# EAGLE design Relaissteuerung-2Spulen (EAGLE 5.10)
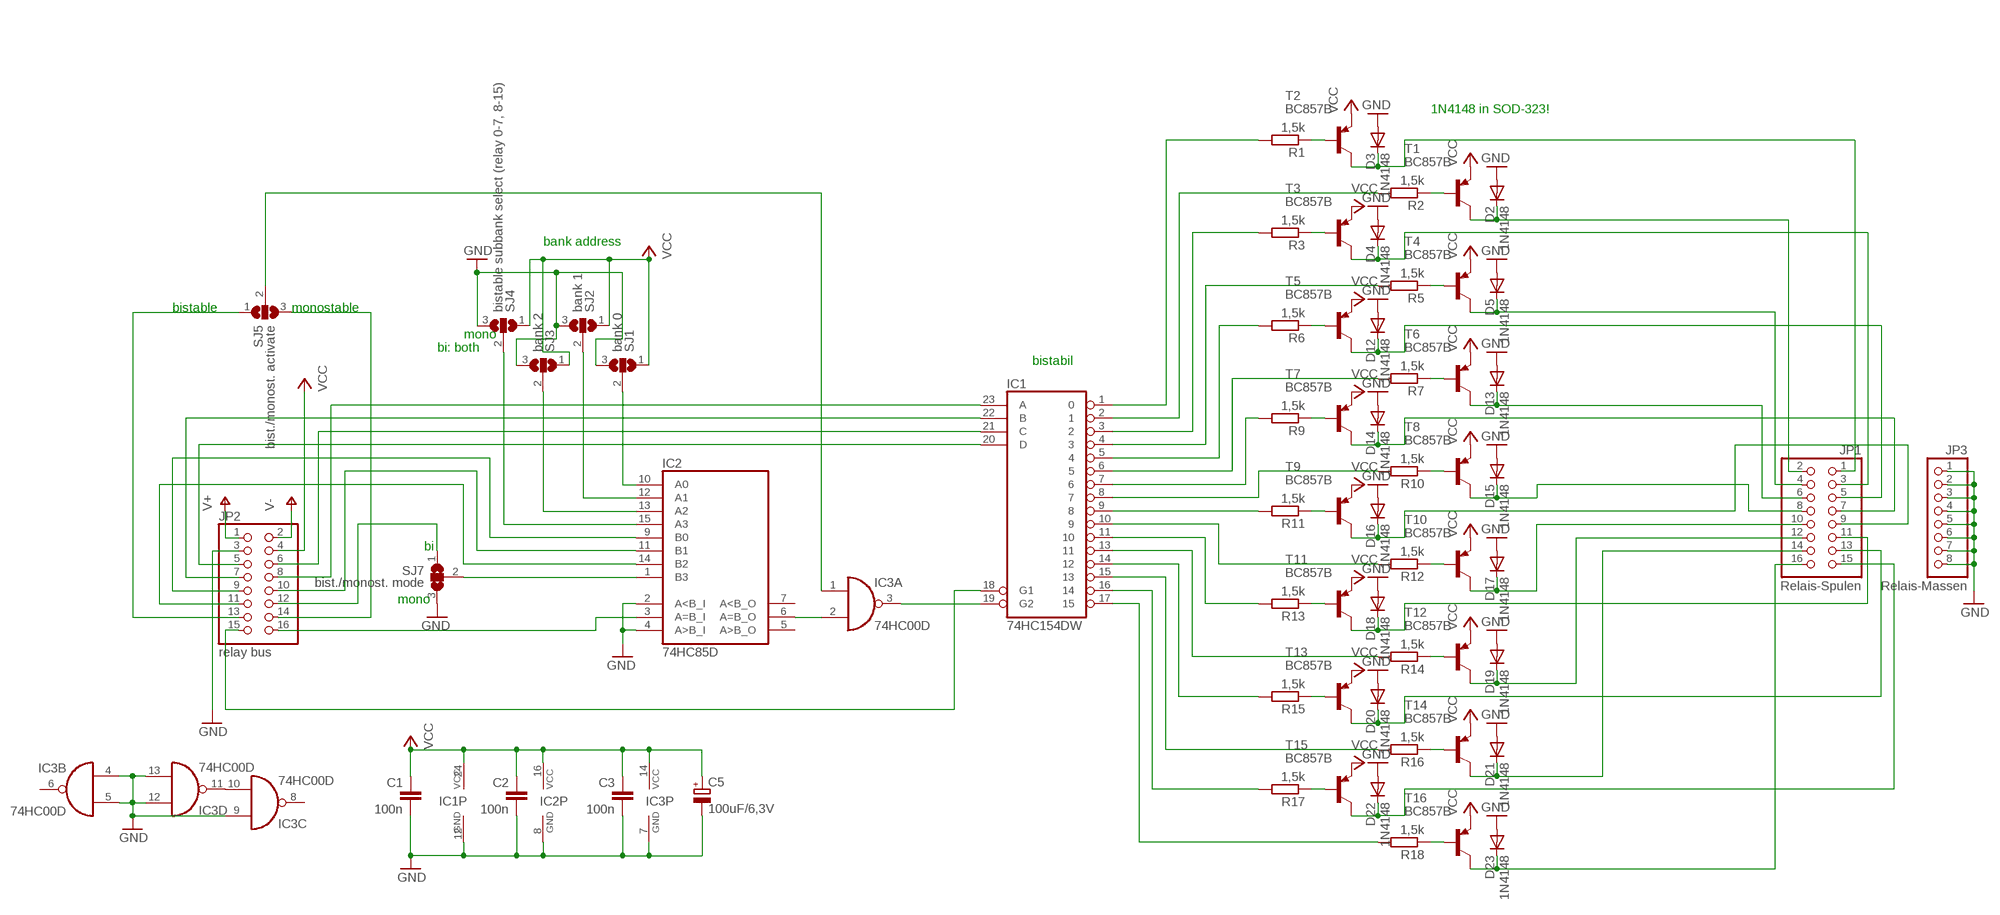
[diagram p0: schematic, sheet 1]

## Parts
C1  100n  C-EUC0805  [C0805]
C2  100n  C-EUC0805  [C0805]
C3  100n  C-EUC0805  [C0805]
C5  100uF/6,3V  CPOL-EUE5-5  [E5-5]
D2  1N4148  1N4148DO35-7  [DO35-7]
D3  1N4148  1N4148DO35-7  [DO35-7]
D4  1N4148  1N4148DO35-7  [DO35-7]
D5  1N4148  1N4148DO35-7  [DO35-7]
D12  1N4148  1N4148DO35-7  [DO35-7]
D13  1N4148  1N4148DO35-7  [DO35-7]
D14  1N4148  1N4148DO35-7  [DO35-7]
D15  1N4148  1N4148DO35-7  [DO35-7]
D16  1N4148  1N4148DO35-7  [DO35-7]
D17  1N4148  1N4148DO35-7  [DO35-7]
D18  1N4148  1N4148DO35-7  [DO35-7]
D19  1N4148  1N4148DO35-7  [DO35-7]
D20  1N4148  1N4148DO35-7  [DO35-7]
D21  1N4148  1N4148DO35-7  [DO35-7]
D22  1N4148  1N4148DO35-7  [DO35-7]
D23  1N4148  1N4148DO35-7  [DO35-7]
IC1  74HC154DW  [SO24W]
IC2  74HC85D  [SO16]
IC3  74HC00D  [SO14]
JP1  Relais-Spulen  PINHD-2X8/90  [2X08/90]
JP2  relay bus  PINHD-2X8/90  [2X08/90]
JP3  Relais-Massen  PINHD-1X8/90  [1X08/90]
R1  1,5k  R-EU_R0805  [R0805]
R2  1,5k  R-EU_R0805  [R0805]
R3  1,5k  R-EU_R0805  [R0805]
R5  1,5k  R-EU_R0805  [R0805]
R6  1,5k  R-EU_R0805  [R0805]
R7  1,5k  R-EU_R0805  [R0805]
R9  1,5k  R-EU_R0805  [R0805]
R10  1,5k  R-EU_R0805  [R0805]
R11  1,5k  R-EU_R0805  [R0805]
R12  1,5k  R-EU_R0805  [R0805]
R13  1,5k  R-EU_R0805  [R0805]
R14  1,5k  R-EU_R0805  [R0805]
R15  1,5k  R-EU_R0805  [R0805]
R16  1,5k  R-EU_R0805  [R0805]
R17  1,5k  R-EU_R0805  [R0805]
R18  1,5k  R-EU_R0805  [R0805]
SJ1  bank 0  SJ2W  [SJ_2]
SJ2  bank 1  SJ2W  [SJ_2]
SJ3  bank 2  SJ2W  [SJ_2]
SJ4  bistable subbank select (relay 0-7, 8-15)  SJ2W  [SJ_2]
SJ5  bist./monost. activate  SJ2W  [SJ_2]
SJ7  bist./monost. mode  SJ2W  [SJ_2]
T1  BC857B  BC857B-PNP-SOT23-BEC  [SOT23-BEC]
T2  BC857B  BC857B-PNP-SOT23-BEC  [SOT23-BEC]
T3  BC857B  BC857B-PNP-SOT23-BEC  [SOT23-BEC]
T4  BC857B  BC857B-PNP-SOT23-BEC  [SOT23-BEC]
T5  BC857B  BC857B-PNP-SOT23-BEC  [SOT23-BEC]
T6  BC857B  BC857B-PNP-SOT23-BEC  [SOT23-BEC]
T7  BC857B  BC857B-PNP-SOT23-BEC  [SOT23-BEC]
T8  BC857B  BC857B-PNP-SOT23-BEC  [SOT23-BEC]
T9  BC857B  BC857B-PNP-SOT23-BEC  [SOT23-BEC]
T10  BC857B  BC857B-PNP-SOT23-BEC  [SOT23-BEC]
T11  BC857B  BC857B-PNP-SOT23-BEC  [SOT23-BEC]
T12  BC857B  BC857B-PNP-SOT23-BEC  [SOT23-BEC]
T13  BC857B  BC857B-PNP-SOT23-BEC  [SOT23-BEC]
T14  BC857B  BC857B-PNP-SOT23-BEC  [SOT23-BEC]
T15  BC857B  BC857B-PNP-SOT23-BEC  [SOT23-BEC]
T16  BC857B  BC857B-PNP-SOT23-BEC  [SOT23-BEC]

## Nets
GND: C1.2 C2.2 C3.2 C5.- D2.A D3.A D4.A D5.A D12.A D13.A D14.A D15.A D16.A D17.A D18.A D19.A D20.A D21.A D22.A D23.A IC1.12(GND) IC2.2(A<B_I) IC2.4(A>B_I) IC2.8(GND) IC3.4(B:I0) IC3.5(B:I1) IC3.7(P:GND) IC3.9(C:I0) IC3.12(D:I0) IC3.13(D:I1) JP2.3 JP3.1 JP3.2 JP3.3 JP3.4 JP3.5 JP3.6 JP3.7 JP3.8 SJ1.3 SJ2.3 SJ3.3 SJ4.3 SJ7.3
N$1: IC2.10(A0) SJ1.2
N$3: IC1.22(B) JP2.7
N$4: IC1.21(C) JP2.6
N$5: IC1.20(D) JP2.5
N$6: IC2.3(A=B_I) JP2.16
N$7: IC2.12(A1) SJ2.2
N$9: IC2.6(A=B_O) IC3.2(A:I1)
N$10: D3.C JP1.1 T2.C
N$11: R2.1 T1.B
N$12: D2.C JP1.2 T1.C
N$13: R3.1 T3.B
N$14: D4.C JP1.3 T3.C
N$15: R5.1 T4.B
N$16: D5.C JP1.4 T4.C
N$17: R11.1 T9.B
N$18: IC2.13(A2) SJ3.2
N$19: R6.1 T5.B
N$20: D12.C JP1.5 T5.C
N$21: R7.1 T6.B
N$22: R1.1 T2.B
N$23: D13.C JP1.6 T6.C
N$24: R9.1 T7.B
N$25: D14.C JP1.7 T7.C
N$26: R10.1 T8.B
N$27: IC1.1 R1.2
N$28: D15.C JP1.8 T8.C
N$29: D16.C JP1.9 T9.C
N$30: IC1.2 R2.2
N$31: IC1.3 R3.2
N$32: IC1.4 R5.2
N$33: IC1.5 R6.2
N$34: R12.1 T10.B
N$35: D17.C JP1.10 T10.C
N$36: R13.1 T11.B
N$37: D18.C JP1.11 T11.C
N$38: R14.1 T12.B
N$39: IC1.6 R7.2
N$40: IC1.7 R9.2
N$41: D19.C JP1.12 T12.C
N$42: R15.1 T13.B
N$43: D20.C JP1.13 T13.C
N$44: R16.1 T14.B
N$45: D21.C JP1.14 T14.C
N$46: R17.1 T15.B
N$47: D22.C JP1.15 T15.C
N$48: R18.1 T16.B
N$49: D23.C JP1.16 T16.C
N$50: IC1.8 R10.2
N$51: IC1.9 R11.2
N$52: IC1.10 R12.2
N$53: IC1.11 R13.2
N$54: IC1.13 R14.2
N$55: IC1.14 R15.2
N$56: IC1.15 R16.2
N$57: IC1.16 R17.2
N$58: IC1.17 R18.2
N$59: IC2.15(A3) SJ4.2
N$60: IC2.1(B3) SJ7.2
N$62: IC1.19(G2) IC3.3(A:O)
N$63: IC1.18(G1) JP2.15
N$64: IC3.1(A:I0) SJ5.2
N$65: JP2.14 SJ5.3
N$66: JP2.13 SJ5.1
N$67: JP2.12 SJ7.1
N$68: IC2.9(B0) JP2.9
N$69: IC2.11(B1) JP2.10
N$70: IC2.14(B2) JP2.11
N$71: IC3.10(C:I1) IC3.11(D:O)
N$75: IC1.23(A) JP2.8
V+: JP2.1
V-: JP2.2
VCC: C1.1 C2.1 C3.1 C5.+ IC1.24(VCC) IC2.16(VCC) IC3.14(P:VCC) JP2.4 SJ1.1 SJ2.1 SJ3.1 SJ4.1 T1.E T2.E T3.E T4.E T5.E T6.E T7.E T8.E T9.E T10.E T11.E T12.E T13.E T14.E T15.E T16.E
Unconnected: IC2.5(A>B_O) IC2.7(A<B_O) IC3.6(B:O) IC3.8(C:O)

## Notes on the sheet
- 1N4148 in SOD-323!
- bank address
- bistable | monostable
- mono
- bi: both
- bistabil
- bi
- mono

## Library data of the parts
C1-C3 = rcl:C-EU: CAPACITOR, European symbol
C5 = rcl:CPOL-EU: POLARIZED CAPACITOR, European symbol
D2-D5 D12-D23 = diode:1N4148: DIODE
IC1 = 74xx-eu:74*154: 4-line to 16-line data SELECTOR/MULTIPLEXER
IC2 = 74xx-eu:74*85: 4-bit magnitude COMPARATOR
IC3 = 74xx-eu:74*00: Quad 2-input NAND gate
JP1 JP2 = pinhead:PINHD-2X8: PIN HEADER
JP3 = pinhead:PINHD-1X8: PIN HEADER
R1-R3 R5-R7 R9-R18 = rcl:R-EU_: RESISTOR, European symbol
SJ1-SJ5 SJ7 = jumper:SJ2W: SMD solder JUMPER
T1-T16 = transistor:*-PNP-: PNP Transistror

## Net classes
0 default: width 0.15 mm, clearance 0.3 mm
1 Power: width 0.5 mm, clearance 0.3 mm

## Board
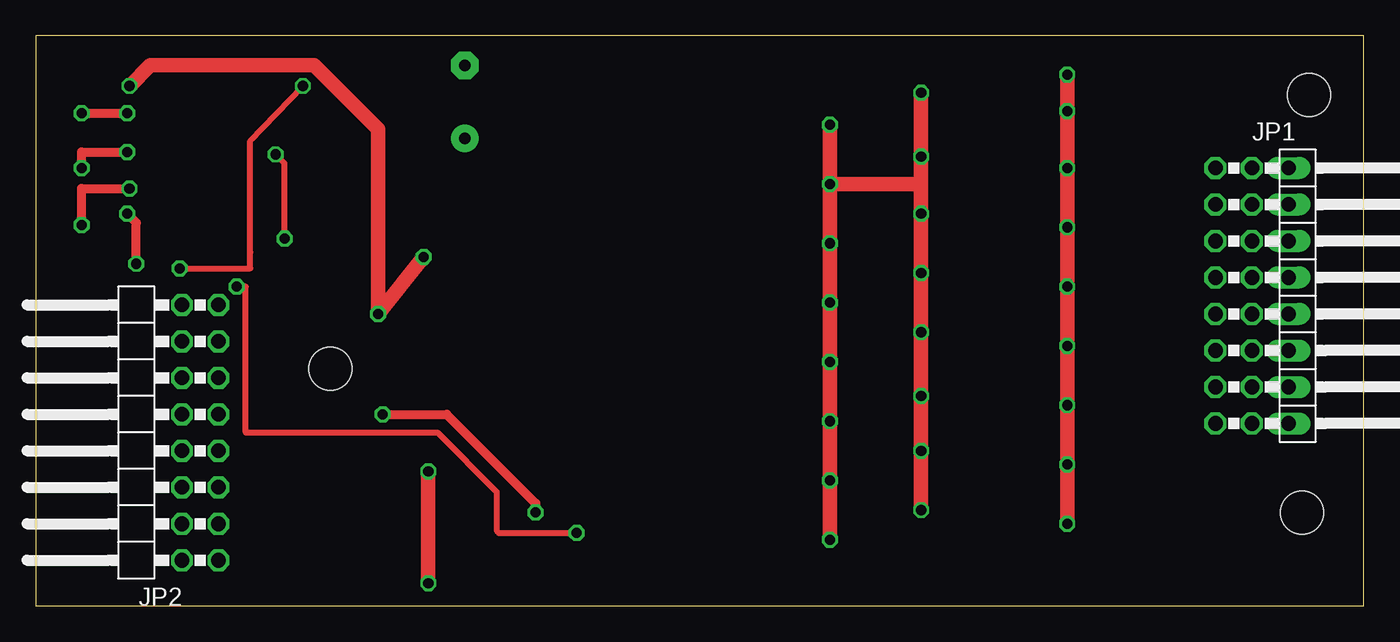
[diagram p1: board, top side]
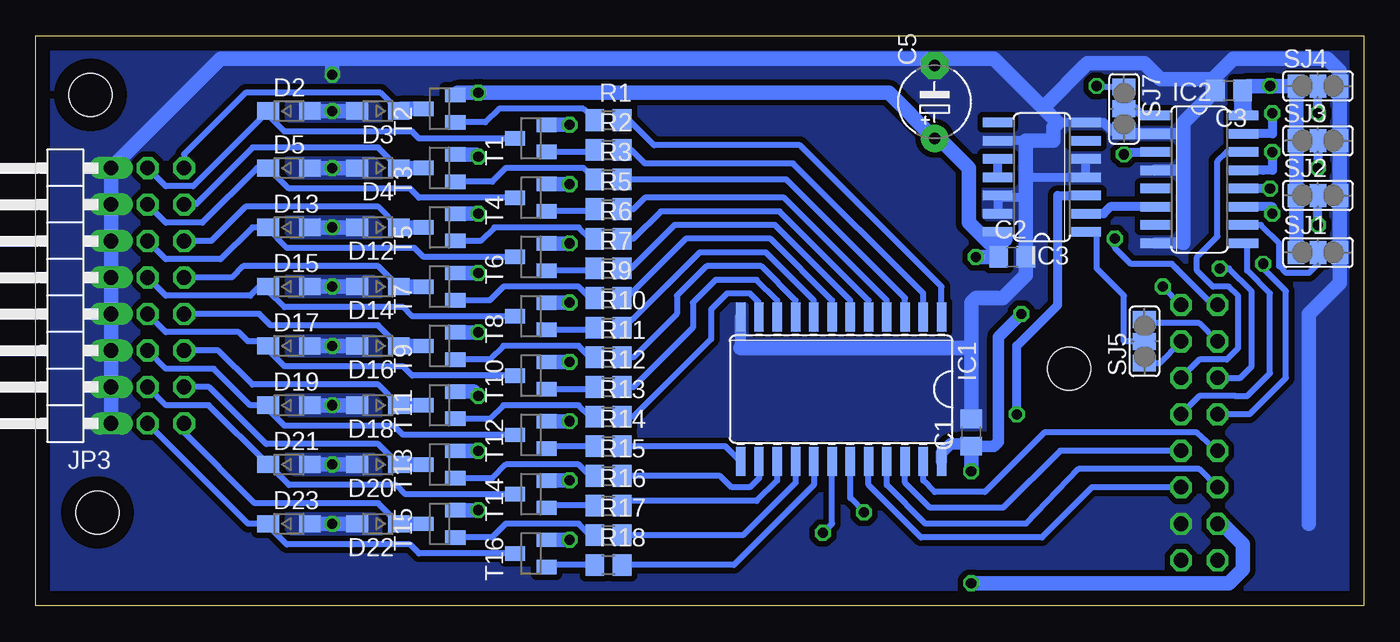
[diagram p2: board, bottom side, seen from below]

Size 92.38 x 39.68 mm. Coordinates in mm from the lower left corner, seen from the top.
Outline: 0,0 92.38,0 92.38,39.68 0,39.68 0,0
Copper layers (1*16): Top 0.035mm / dielectric 1.5mm / Bottom 0.035mm
Design rules "default *": minimum track width 10mil, minimum drill 24mil, track to track 0.25mm, track to pad 0.25mm, pad to pad 0.25mm, via to via 0.25mm, smd to smd 0.25mm, copper to edge 40mil, drill to drill 8mil, minimum pad ring 10mil, minimum via ring 8mil, stop-mask expansion 4mil, vias tented up to drill 0mil, thermal gap 10mil
Holes 3 mm at 20.48,16.51 88.58,35.56 88.11,6.51

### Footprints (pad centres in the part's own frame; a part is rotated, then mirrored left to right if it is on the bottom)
C0805 = smd 1.3 x 1.5: 1 -0.95,0; 2 0.95,0
E5-5 = drill 0.813 pad 1.905 round: + -2.54,0 | drill 0.813 pad 1.905 octagon: - 2.54,0
SOD323-W = smd 1.5 x 1.2: A 1.45,0; C -1.45,0
SO24W = smd 0.66 x 2.032: 1 -6.985,-5.029; 2 -5.715,-5.029; 3 -4.445,-5.029; 4 -3.175,-5.029; 5 -1.905,-5.029; 6 -0.635,-5.029; 7 0.635,-5.029; 8 1.905,-5.029; 9 3.175,-5.029; 10 4.445,-5.029; 11 5.715,-5.029; 12 6.985,-5.029; 13 6.985,5.029; 14 5.715,5.029; 15 4.445,5.029; 16 3.175,5.029; 17 1.905,5.029; 18 0.635,5.029; 19 -0.635,5.029; 20 -1.905,5.029; 21 -3.175,5.029; 22 -4.445,5.029; 23 -5.715,5.029; 24 -6.985,5.029
SO16 = smd 0.66 x 2.032: 1 -4.445,-3.073; 2 -3.175,-3.073; 3 -1.905,-3.073; 4 -0.635,-3.073; 5 0.635,-3.073; 6 1.905,-3.073; 7 3.175,-3.073; 8 4.445,-3.073; 9 4.445,3.073; 10 3.175,3.073; 11 1.905,3.073; 12 0.635,3.073; 13 -0.635,3.073; 14 -1.905,3.073; 15 -3.175,3.073; 16 -4.445,3.073
SO14 = smd 0.66 x 2.032: 1 -3.81,-3.073; 2 -2.54,-3.073; 3 -1.27,-3.073; 4 0,-3.073; 5 1.27,-3.073; 6 2.54,-3.073; 7 3.81,-3.073; 8 3.81,3.073; 9 2.54,3.073; 10 1.27,3.073; 11 0,3.073; 12 -1.27,3.073; 13 -2.54,3.073; 14 -3.81,3.073
2X08/90 = drill 1.016 octagon: 1 -8.89,-6.35; 2 -8.89,-3.81; 3 -6.35,-6.35; 4 -6.35,-3.81; 5 -3.81,-6.35; 6 -3.81,-3.81; 7 -1.27,-6.35; 8 -1.27,-3.81; 9 1.27,-6.35; 10 1.27,-3.81; 11 3.81,-6.35; 12 3.81,-3.81; 13 6.35,-6.35; 14 6.35,-3.81; 15 8.89,-6.35; 16 8.89,-3.81
1X08/90 = drill 1.016 long: 1 -8.89,-3.81; 2 -6.35,-3.81; 3 -3.81,-3.81; 4 -1.27,-3.81; 5 1.27,-3.81; 6 3.81,-3.81; 7 6.35,-3.81; 8 8.89,-3.81
R0805 = smd 1.3 x 1.5: 1 -0.95,0; 2 0.95,0
SJ_2 = smd 1.168 x 1.6: 1 -1.524,0; 2 0,0; 3 1.524,0
SOT23-BEC = smd 1 x 1.4: B -0.95,-1.1; C 0,1.1; E 0.95,-1.1

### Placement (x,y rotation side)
C1  27.3,12.06 90 bottom
C2  24.45,24.29 0 bottom
C3  9.37,35.88 180 bottom
C5  29.84,35.08 90 bottom
D2  1N4148  [SOD323-W]  74.77,34.45 0 bottom
D3  1N4148  [SOD323-W]  68.58,34.45 180 bottom
D4  1N4148  [SOD323-W]  68.58,30.48 180 bottom
D5  1N4148  [SOD323-W]  74.77,30.48 0 bottom
D12  1N4148  [SOD323-W]  68.58,26.35 180 bottom
D13  1N4148  [SOD323-W]  74.77,26.35 0 bottom
D14  1N4148  [SOD323-W]  68.58,22.23 180 bottom
D15  1N4148  [SOD323-W]  74.77,22.23 0 bottom
D16  1N4148  [SOD323-W]  68.58,18.1 180 bottom
D17  1N4148  [SOD323-W]  74.77,18.1 0 bottom
D18  1N4148  [SOD323-W]  68.58,13.97 180 bottom
D19  1N4148  [SOD323-W]  74.77,13.97 0 bottom
D20  1N4148  [SOD323-W]  68.58,9.84 180 bottom
D21  1N4148  [SOD323-W]  74.77,9.84 0 bottom
D22  1N4148  [SOD323-W]  68.58,5.71 180 bottom
D23  1N4148  [SOD323-W]  74.77,5.71 0 bottom
IC1  36.35,15.08 180 bottom
IC2  11.43,29.69 270 bottom
IC3  22.38,29.84 90 bottom
JP1  88.42,21.59 270 top
JP2  6.35,12.07 90 top
JP3  90.96,21.59 90 bottom
R1  52.55,33.81 0 bottom
R2  52.55,31.75 0 bottom
R3  52.55,29.69 0 bottom
R5  52.55,27.62 0 bottom
R6  52.55,25.56 0 bottom
R7  52.55,23.5 0 bottom
R9  52.55,21.43 0 bottom
R10  52.55,19.37 0 bottom
R11  52.55,17.3 0 bottom
R12  52.55,15.24 0 bottom
R13  52.55,13.18 0 bottom
R14  52.55,11.11 0 bottom
R15  52.55,9.05 0 bottom
R16  52.55,6.99 0 bottom
R17  52.55,4.92 0 bottom
R18  52.55,2.86 0 bottom
SJ1  3.17,24.61 0 bottom
SJ2  3.17,28.58 0 bottom
SJ3  3.17,32.39 0 bottom
SJ4  3.17,36.2 0 bottom
SJ5  15.24,18.42 90 bottom
SJ7  16.67,34.61 270 bottom
T1  57.94,32.54 90 bottom
T2  64.29,34.61 90 bottom
T3  64.29,30.48 90 bottom
T4  57.94,28.42 90 bottom
T5  64.29,26.35 90 bottom
T6  57.94,24.29 90 bottom
T7  64.29,22.23 90 bottom
T8  57.94,20.16 90 bottom
T9  64.29,18.1 90 bottom
T10  57.94,16.03 90 bottom
T11  64.29,13.97 90 bottom
T12  57.94,11.91 90 bottom
T13  64.29,9.84 90 bottom
T14  57.94,7.78 90 bottom
T15  64.29,5.71 90 bottom
T16  57.94,3.65 90 bottom

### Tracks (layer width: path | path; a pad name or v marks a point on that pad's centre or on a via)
GND  (via drill 0.7)
  Top 1.016: v71.75,5.71 v71.75,9.84 v71.75,13.97 v71.75,18.1 v71.75,22.23 v71.75,26.35 v71.75,30.48 v71.75,34.45 v71.75,36.99
  Bottom 0.61: IC3.13 IC3.12 25.3,28.42 23.5,28.42 | 21.59,32.38 IC3.9 | 21.43,33.81 21.27,33.66 IC3.7 18.1,33.66 17.46,33.02 16.73,33.02 SJ7.3 | 23.5,30.04 23.3,29.84 IC3.4 IC3.5
  Bottom 0.813: 43.34,17.94 IC1.12 | 12.54,25.24 IC2.8 | 12.54,33.66 12.54,32.86 IC2.2 16.45,32.86 SJ7.3 | 12.54,30.32 IC2.4
  Bottom 1.016: D22.A v71.75,5.71 D23.A | D20.A v71.75,9.84 D21.A | D18.A v71.75,13.97 D19.A | D16.A | D16.A v71.75,18.1 D17.A | D14.A v71.75,22.23 D15.A | D12.A v71.75,26.35 D13.A | D3.A v71.75,34.45 D2.A | JP3.1 JP3.2 JP3.3 JP3.4 JP3.5 JP3.6 JP3.7 JP3.8 79.53,38.1 71.91,38.1 | 10.48,36.67 10.48,36.04 C3.2 12.54,33.66 12.54,30.32 12.54,25.24 | 23.5,28.51 23.5,30.04 23.5,32.38 21.59,32.38 21.59,33.34 21.27,33.66 | 23.5,28.51 23.5,28.42 C2.2 23.5,23.02 25.08,21.43 26.99,21.43 27.3,21.11 27.3,17.78 | 23.5,28.51 23.59,28.42 | 10.48,36.67 14.13,36.67 15.24,37.78 19.21,37.78 22.23,34.77 | 21.43,33.81 25.72,38.1 30.32,38.1 | D4.A v71.75,30.48 D5.A | 3.81,5.71 3.81,20.32 1.65,22.48 SJ1.3 SJ2.3 SJ3.3 SJ4.3 1.65,37.21 2.54,38.1 9.05,38.1 10.48,36.67 | v71.75,36.99 71.75,37.94 71.91,38.1 | 27.3,17.78 C1.2 | 43.34,17.94 27.46,17.94 27.3,17.78 | 30.32,38.1 C5.- | 30.32,38.1 71.91,38.1
  pour Bottom (isolate 0.4, no thermals): 0,0 92.71,0 91.44,39.69 0,39.69
N$1
  Bottom 0.406: 3.17,24.13 SJ1.2 3.17,23.81 3.81,23.18 5.4,23.18 5.87,23.65 5.87,25.24 7.14,26.51 IC2.10
N$3
  Bottom 0.406: JP2.7 21.11,10.79 25.08,6.83 30.16,6.83 31.91,8.57 IC1.22 | IC1.22
N$4
  Bottom 0.406: JP2.6 11.43,9.53 19.84,9.53 23.5,5.71 30.48,5.71 33.18,8.41 IC1.21 | IC1.21
N$5
  Bottom 0.406: JP2.5 18.89,8.26 22.38,4.76 30.8,4.76 34.45,8.41 IC1.20 | IC1.20
N$6  (via drill 0.7)
  Top 0.406: v17.3,25.56 17.3,30.8 v16.67,31.43
  Bottom 0.406: v17.3,25.56 17.3,24.92 16.19,23.81 13.34,23.81 13.02,23.5 10.48,20.95 JP2.16
  Bottom 0.61: IC2.3 16.51,31.59 v16.67,31.43
N$7  (via drill 0.7)
  Top 0.61: v6.51,29.05 3.17,29.05 v3.17,26.51
  Bottom 0.61: v6.51,29.05 IC2.12 | v3.17,26.51 SJ2.2
N$9
  Bottom 0.61: IC2.6 17.62,27.78 18.1,27.3 IC3.2
N$10
  Bottom 0.406: D3.C 68.4,35.72 77.79,35.72 82.07,31.43 JP1.1
  Bottom 1.016: D3.C | D3.C 66.97,34.61 T2.C
N$11
  Bottom 0.406: R2.1 53.65,31.59 T1.B
N$12
  Bottom 0.406: JP1.2 83.34,29.21 81.44,29.21 76.22,34.43 D2.C | D2.C 76.52,34.45 | D2.C 76.22,34.15 75.09,33.02 66.2,33.02 65.72,32.54 60.01,32.54 T1.C
N$13
  Bottom 0.406: R3.1 54.29,30.48 59.69,30.48 60.64,29.53 T3.B
N$14
  Bottom 0.406: D4.C 68.56,31.91 77.31,31.91 81.28,27.94 JP1.3
  Bottom 1.016: T3.C D4.C | D4.C
N$15
  Bottom 0.406: R5.1 53.65,27.47 T4.B
N$16
  Bottom 0.406: JP1.4 83.34,26.67 80.8,26.67 76.99,30.48 D5.C 74.79,29.05 73.66,29.05 68.26,29.05 66.36,29.05 65.72,28.42 T4.C
N$17
  Bottom 0.406: T9.B 60.8,17.15 59.85,18.1 54.61,18.1 53.82,17.3 R11.1
N$18  (via drill 0.7)
  Top 0.61: v3.17,30.48 3.17,31.59 v6.35,31.59
  Bottom 0.61: IC2.13 6.99,30.32 6.35,30.32 v6.35,31.59 | SJ3.2 v3.17,30.48
N$19
  Bottom 0.406: T5.B 61.43,25.4 60.48,26.35 54.61,26.35 53.82,25.56 R6.1
N$20
  Bottom 0.406: D12.C 68.56,27.78 77.79,27.78 80.17,25.4 JP1.5
  Bottom 1.016: T5.C D12.C
N$21
  Bottom 0.406: T6.B 53.65,23.34 R7.1
N$22
  Bottom 0.406: R1.1 54.29,34.61 60.17,34.61 61.12,33.66 T2.B
N$23
  Bottom 0.406: JP1.6 83.34,24.13 79.53,24.13 77.31,26.35 D13.C 76.22,26.21 74.93,24.92 66.04,24.92 65.41,24.29 T6.C
N$24
  Bottom 0.406: T7.B 60.8,21.27 59.85,22.23 54.61,22.23 53.82,21.43 R9.1
N$25
  Bottom 0.406: D14.C 68.56,23.65 77.95,23.65 78.74,22.86 JP1.7
  Bottom 1.016: T7.C D14.C
N$26
  Bottom 0.406: T8.B 53.65,19.21 R10.1
N$27
  Bottom 0.406: IC1.1 29.37,22.23 39.21,32.07 49.37,32.07 51.12,33.81 R1.2
N$28
  Bottom 0.406: JP1.8 83.34,21.59 77.47,21.59 76.83,22.23 D15.C 76.22,21.93 75.09,20.8 66.83,20.8 66.2,20.16 T8.C
N$29
  Bottom 0.406: D16.C 68.56,19.53 76.04,19.53 76.83,20.32 JP1.9
  Bottom 1.016: T9.C D16.C
N$30
  Bottom 0.406: IC1.2 30.64,21.75 39.69,30.8 50.01,30.8 50.96,31.75 R2.2
N$31
  Bottom 0.406: IC1.3 31.91,21.43 40.16,29.69 R3.2
N$32
  Bottom 0.406: IC1.4 33.18,21.27 40.32,28.42 50.01,28.42 50.8,27.62 R5.2
N$33
  Bottom 0.406: IC1.5 34.45,21.27 40.64,27.46 48.9,27.46 50.8,25.56 R6.2 | R6.2
N$34
  Bottom 0.406: T10.B 53.65,15.08 R12.1
N$35
  Bottom 0.406: JP1.10 83.34,19.05 78.26,19.05 77.63,18.41 76.54,18.41 D17.C 76.22,17.8 75.09,16.67 66.83,16.67 66.2,16.03 60.33,16.03 | 60.33,16.03 | T10.C 60.33,16.03
N$36
  Bottom 0.406: T11.B 60.8,13.02 59.85,13.97 54.61,13.97 53.82,13.18 R13.1
N$37
  Bottom 0.406: D18.C 68.56,15.4 77.31,15.4 79.69,17.78 JP1.11
  Bottom 1.016: T11.C D18.C
N$38
  Bottom 0.406: T12.B 56.69,11.11 R14.1
N$39
  Bottom 0.406: IC1.6 35.72,21.27 40.96,26.51 47.94,26.51 50.96,23.5 R7.2 | R7.2
N$40
  Bottom 0.406: IC1.7 36.99,21.27 41.27,25.56 47.15,25.56 51.28,21.43 R9.2 | R9.2
N$41
  Bottom 0.406: JP1.12 83.34,16.51 80.01,16.51 77.47,13.97 D19.C 76.22,13.67 75.09,12.54 67.47,12.54 66.83,11.91 T12.C
N$42
  Bottom 0.406: T13.B 60.64,8.89 59.69,9.84 54.61,9.84 53.82,9.05 R15.1
N$43
  Bottom 0.406: D20.C 68.56,11.27 76.36,11.27 80.33,15.24 JP1.13
  Bottom 1.016: T13.C D20.C | D20.C
N$44
  Bottom 0.406: T14.B 56.69,6.99 R16.1
N$45
  Bottom 0.406: JP1.14 83.34,13.97 80.35,13.97 D21.C 76.2,9.84 74.77,8.41 67.31,8.41 66.67,7.78 T14.C
N$46
  Bottom 0.406: T15.B 60.64,4.76 59.69,5.71 54.61,5.71 53.82,4.92 R17.1
N$47
  Bottom 0.406: D22.C 68.56,7.14 77.15,7.14 82.07,12.06 JP1.15
  Bottom 1.016: T15.C D22.C
N$48
  Bottom 0.406: T16.B 56.69,2.86 R18.1
N$49
  Bottom 0.406: D23.C 76.22,5.58 | D23.C 77.63,5.71 JP1.16 | T16.C 65.72,3.65 66.36,4.29 74.93,4.29 76.22,5.58 | 76.22,5.58 D23.C
N$50
  Bottom 0.406: R10.2 | IC1.8 38.26,21.27 41.59,24.61 46.2,24.61 49.53,21.27 49.85,20.95 50.8,20 R10.2 | R10.2 51.44,19.37
N$51
  Bottom 0.406: IC1.9 39.53,21.27 41.91,23.65 45.72,23.65 47.78,21.59 47.78,20.32 50.8,17.3 R11.2 | R11.2
N$52
  Bottom 0.406: 51.28,15.56 R12.2 50.8,15.24 46.67,19.37 46.67,21.11 45.09,22.7 42.23,22.7 40.8,21.27 IC1.10
N$53
  Bottom 0.406: IC1.11 42.07,21.11 42.7,21.75 44.29,21.75 45.4,20.64 45.4,18.57 50.8,13.18 R13.2
N$54
  Bottom 0.406: IC1.13 44.4,11.11 R14.2
N$55
  Bottom 0.406: IC1.14 42.07,8.89 42.7,8.26 43.97,8.26 44.77,9.05 R15.2
N$56
  Bottom 0.406: IC1.15 40.8,8.73 42.23,7.3 51.28,7.3 R16.2
N$57
  Bottom 0.406: IC1.16 39.53,8.57 43.18,4.92 R17.2
N$58
  Bottom 0.406: IC1.17 38.26,8.41 43.81,2.86 R18.2
N$59  (via drill 0.7)
  Top 0.61: v3.17,34.29 v6.35,34.29
  Bottom 0.61: IC2.15 6.35,32.86 v6.35,34.29 | v3.17,34.29 SJ4.2
N$60
  Bottom 0.61: IC2.1 15.4,34.13 15.88,34.61 SJ7.2
N$62  (via drill 0.7)
  Top 0.61: v24.13,13.34 28.57,13.34 34.77,7.14 v34.77,6.51
  Bottom 0.406: IC1.19 35.72,7.51 34.72,6.51 v34.77,6.51
  Bottom 0.61: IC3.3 21.27,28.57 21.27,20.95 24.13,18.1 v24.13,13.34
N$63  (via drill 0.7)
  Top 0.406: 14.61,22.23 v13.97,22.23 | 14.61,22.23 | 14.61,22.23 14.61,12.06 27.94,12.06 32.07,7.94 | 32.07,7.94 | 32.07,7.94 32.07,5.24 32.23,5.08 v37.62,5.08
  Bottom 0.406: v13.97,22.23 JP2.15 | v37.62,5.08 36.99,5.71 IC1.18
N$64
  Bottom 0.406: 19.37,25.98 IC3.1 18.57,26.04 18.57,23.5 16.67,21.59 16.67,18.41 SJ5.2
N$65
  Bottom 0.406: JP2.14 11.43,19.68 14.99,19.68 SJ5.3
N$66
  Bottom 0.406: SJ5.1 14.22,16.89 JP2.13
N$67  (via drill 0.7)
  Top 0.406: v18.57,36.2 14.92,32.38 14.92,24.61 14.92,23.5 v10,23.5
  Bottom 0.406: SJ7.1 18.51,36.13 v18.57,36.2 | v10,23.5 9.37,23.5 7.78,21.91 7.78,16.67 8.57,15.88 JP2.12 | JP2.12
N$68
  Bottom 0.406: JP2.9 11.43,14.61 8.89,14.61 | IC2.9 8.1,25.24 8.1,23.34 6.51,21.75 6.51,16.19 8.1,14.61 8.89,14.61 | 8.89,14.61
N$69  (via drill 0.7)
  Top 0.61: v6.99,23.81 6.99,26.67 v6.35,27.3
  Bottom 0.406: JP2.10 7.94,13.34 5.4,15.88 5.4,21.91 6.99,23.5 v6.99,23.81
  Bottom 0.61: v6.35,27.3 6.35,27.78 IC2.11
N$70
  Bottom 0.406: JP2.11 11.43,17.14 9.53,17.14 8.73,17.94 8.73,21.59 9.37,22.23 10.48,22.23 11.59,23.34 11.59,24.29 10.16,25.72 10.16,30.96 9.53,31.59 IC2.14
N$71
  Bottom 0.61: IC3.11 IC3.10
N$75
  Bottom 0.406: JP2.8 11.59,12.06 22.23,12.06 26.35,7.94 29.84,7.94 30.64,8.73 IC1.23
VCC  (via drill 0.7)
  Top 1.016: 61.59,29.37 v61.59,31.27 v61.59,35.72 | v61.59,6.67 v61.59,10.79 v61.59,14.61 v61.59,19.05 v61.59,23.18 v61.59,27.3 61.59,29.37 | v55.24,4.6 v55.24,8.73 v55.24,12.86 v55.24,16.99 v55.24,21.11 v55.24,25.24 v55.24,29.37 | v55.24,29.37 | 61.59,29.37 v55.24,29.37 | v27.3,1.59 v27.3,9.37 | v26.99,24.29 v23.81,20.32 23.81,33.18 19.37,37.62 7.94,37.62 v6.51,36.2 | v55.24,29.37 v55.24,33.5
  Bottom 0.406: 25.72,24.61 25.56,24.45
  Bottom 0.61: 25.46,24.35 IC3.14 25.08,26.04 24.77,25.72 | C2.1 25.46,24.35 | 24.77,25.72 26.19,25.72 26.19,25.56 26.04,25.24 25.72,25.08 25.08,25.08 | 24.77,25.72 24.77,25.4 24.92,25.24 | 25.46,24.35 25.72,24.61 | C3.1 8.36,35.82 | 8.36,35.82 IC2.16 | 8.36,35.82 8.73,35.44 8.73,34.29 7.94,34.29 8.1,34.45 8.1,35.72 8.26,35.88 C3.1
  Bottom 0.813: IC1.24 29.37,10.64 28.73,11.27 27.46,11.27 C1.1 25.71,11.12 25.4,11.43 25.4,18.73 v23.81,20.32
  Bottom 1.016: T3.E 61.75,31.43 v61.59,31.27 | T4.E 55.88,29.37 v55.24,29.37 | SJ1.1 SJ2.1 SJ3.1 SJ4.1 v6.51,36.2 8.1,36.2 C3.1 | C2.1 25.24,24.29 v26.99,24.29 | v61.59,27.3 v61.6,27.3 T5.E | v61.59,23.18 v61.6,23.18 T7.E | v61.59,19.05 v61.6,19.05 T9.E | v55.24,25.24 v55.25,25.24 T6.E | v55.24,21.11 v55.25,21.11 T8.E | v55.24,16.99 v55.25,16.98 T10.E | v55.24,12.86 v55.25,12.86 T12.E | v61.59,14.61 61.91,14.92 T11.E | v55.24,8.73 v55.25,8.73 T14.E | v55.24,4.6 v55.25,4.6 T16.E | v61.59,6.67 v61.6,6.67 T15.E | v61.59,10.79 v61.6,10.79 T13.E | 26.04,25.24 27.46,26.67 27.46,30.48 29.53,32.54 C5.+ 33.02,35.72 v61.59,35.72 63.03,35.72 T2.E | v27.3,9.37 C1.1 | C1.1 | v55.24,33.5 v55.25,33.49 T1.E | v27.3,1.59 15.08,1.59 13.49,1.59 9.37,1.59 8.41,2.54 8.41,4.29 9.84,5.71 JP2.4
